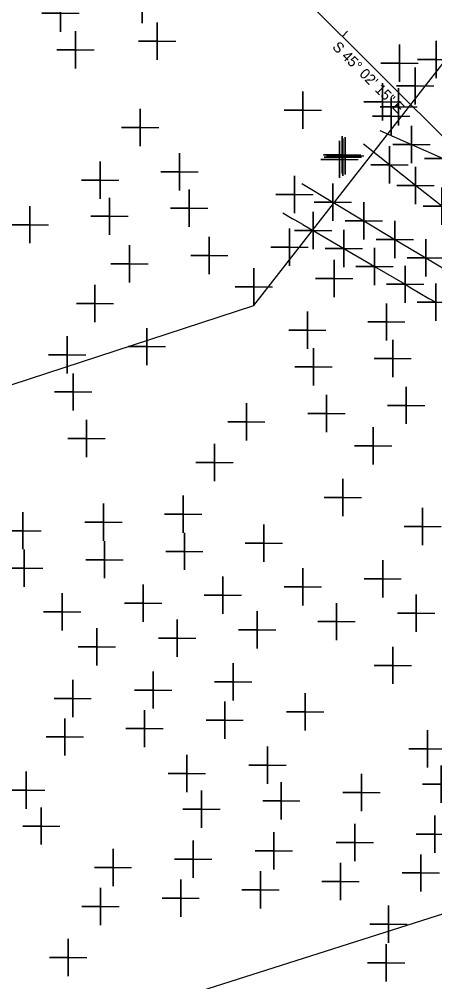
# Model space of a CAD drawing. Extents: x 2260968 to 2264340, y 653057 to 655850.
# Drawn here: x 2261248.1 to 2261303.8, y 655413.7 to 655542.8 of the extents above; entities that cross this region are included whole.
import ezdxf

# ---------------------------------------------------------------- set-up
doc = ezdxf.new("R2010")
doc.units = 0
for name, color, linetype in [('CL_X_Construction', 7, 'Continuous'), ('Default', 7, 'Continuous'), ('GE_X_CL_10', 7, 'Continuous'), ('GK_Patterns2', 7, 'Continuous')]:
    doc.layers.add(name, color=color, linetype=linetype)

msp = doc.modelspace()

# ---------------------------------------------------------------- linework, layer by layer
at = {"layer": 'CL_X_Construction'}
msp.add_line((2261256.04, 655575.83), (2261337.92, 655494.06), dxfattribs=at)
msp.add_line((2261256.04, 655575.83), (2261337.92, 655494.06), dxfattribs=at)
at = {"layer": 'Default'}
for points in [[(2261264.57, 655544.78), (2261264.57, 655547.28), (2261264.57, 655544.78), (2261262.07, 655544.78), (2261264.57, 655544.78), (2261264.57, 655542.28), (2261264.57, 655544.78), (2261267.07, 655544.78)], [(2261253.62, 655543.62), (2261253.62, 655546.12), (2261253.62, 655543.62), (2261251.12, 655543.62), (2261253.62, 655543.62), (2261253.62, 655541.12), (2261253.62, 655543.62), (2261256.12, 655543.62)], [(2261266.58, 655539.87), (2261266.58, 655542.37), (2261266.58, 655539.87), (2261264.08, 655539.87), (2261266.58, 655539.87), (2261266.58, 655537.37), (2261266.58, 655539.87), (2261269.08, 655539.87)], [(2261255.61, 655538.7), (2261255.61, 655541.2), (2261255.61, 655538.7), (2261253.11, 655538.7), (2261255.61, 655538.7), (2261255.61, 655536.2), (2261255.61, 655538.7), (2261258.11, 655538.7)], [(2261299.09, 655536.92), (2261299.09, 655539.42), (2261299.09, 655536.92), (2261296.59, 655536.92), (2261299.09, 655536.92), (2261299.09, 655534.42), (2261299.09, 655536.92), (2261301.59, 655536.92)], [(2261303.99, 655537.42), (2261303.99, 655539.92), (2261303.99, 655537.42), (2261301.49, 655537.42), (2261303.99, 655537.42), (2261303.99, 655534.92), (2261303.99, 655537.42), (2261306.49, 655537.42)], [(2261301.17, 655533.85), (2261301.17, 655536.35), (2261301.17, 655533.85), (2261298.67, 655533.85), (2261301.17, 655533.85), (2261301.17, 655531.35), (2261301.17, 655533.85), (2261303.67, 655533.85)], [(2261296.82, 655531.72), (2261296.82, 655534.22), (2261296.82, 655531.72), (2261294.32, 655531.72), (2261296.82, 655531.72), (2261296.82, 655529.22), (2261296.82, 655531.72), (2261299.32, 655531.72)], [(2261286.1, 655530.6), (2261286.1, 655533.1), (2261286.1, 655530.6), (2261283.6, 655530.6), (2261286.1, 655530.6), (2261286.1, 655528.1), (2261286.1, 655530.6), (2261288.6, 655530.6)], [(2261298.97, 655531.06), (2261298.97, 655533.56), (2261298.97, 655531.06), (2261296.47, 655531.06), (2261298.97, 655531.06), (2261298.97, 655528.56), (2261298.97, 655531.06), (2261301.47, 655531.06)], [(2261297.98, 655529.8), (2261297.98, 655532.3), (2261297.98, 655529.8), (2261295.48, 655529.8), (2261297.98, 655529.8), (2261297.98, 655527.3), (2261297.98, 655529.8), (2261300.48, 655529.8)], [(2261264.31, 655528.27), (2261264.31, 655530.77), (2261264.31, 655528.27), (2261261.81, 655528.27), (2261264.31, 655528.27), (2261264.31, 655525.77), (2261264.31, 655528.27), (2261266.81, 655528.27)], [(2261300.7, 655526), (2261300.7, 655528.5), (2261300.7, 655526), (2261298.2, 655526), (2261300.7, 655526), (2261300.7, 655523.5), (2261300.7, 655526), (2261303.2, 655526)], [(2261296.45, 655527.86), (2261300.7, 655526), (2261304.95, 655524.14), (2261309.21, 655522.28), (2261313.46, 655520.42), (2261317.72, 655518.56), (2261321.97, 655516.71), (2261326.22, 655514.85), (2261330.48, 655512.99), (2261334.73, 655511.13), (2261338.99, 655509.27), (2261343.24, 655507.41)], [(2261291.04, 655524.01), (2261291.04, 655526.51), (2261291.04, 655524.01), (2261288.54, 655524.01), (2261291.04, 655524.01), (2261291.04, 655521.51), (2261291.04, 655524.01), (2261293.54, 655524.01)], [(2261291.39, 655524.63), (2261291.39, 655527.13), (2261291.39, 655524.63), (2261288.89, 655524.63), (2261291.39, 655524.63), (2261291.39, 655522.13), (2261291.39, 655524.63), (2261293.89, 655524.63)], [(2261291.48, 655524.29), (2261291.48, 655526.79), (2261291.48, 655524.29), (2261288.98, 655524.29), (2261291.48, 655524.29), (2261291.48, 655521.79), (2261291.48, 655524.29), (2261293.98, 655524.29)], [(2261291.81, 655524.5), (2261291.81, 655527), (2261291.81, 655524.5), (2261289.31, 655524.5), (2261291.81, 655524.5), (2261291.81, 655522), (2261291.81, 655524.5), (2261294.31, 655524.5)], [(2261304.75, 655517.72), (2261301.24, 655520.5), (2261297.74, 655523.28), (2261294.24, 655526.06)], [(2261304.95, 655524.14), (2261304.95, 655526.64), (2261304.95, 655524.14), (2261302.45, 655524.14), (2261304.95, 655524.14), (2261304.95, 655521.64), (2261304.95, 655524.14), (2261307.45, 655524.14)], [(2261269.58, 655522.33), (2261269.58, 655524.83), (2261269.58, 655522.33), (2261267.08, 655522.33), (2261269.58, 655522.33), (2261269.58, 655519.83), (2261269.58, 655522.33), (2261272.08, 655522.33)], [(2261297.74, 655523.28), (2261297.74, 655525.78), (2261297.74, 655523.28), (2261295.24, 655523.28), (2261297.74, 655523.28), (2261297.74, 655520.78), (2261297.74, 655523.28), (2261300.24, 655523.28)], [(2261258.94, 655521.23), (2261258.94, 655523.73), (2261258.94, 655521.23), (2261256.44, 655521.23), (2261258.94, 655521.23), (2261258.94, 655518.73), (2261258.94, 655521.23), (2261261.44, 655521.23)], [(2261301.24, 655520.5), (2261301.24, 655523), (2261301.24, 655520.5), (2261298.74, 655520.5), (2261301.24, 655520.5), (2261301.24, 655518), (2261301.24, 655520.5), (2261303.74, 655520.5)], [(2261285.01, 655519.29), (2261285.01, 655521.79), (2261285.01, 655519.29), (2261282.51, 655519.29), (2261285.01, 655519.29), (2261285.01, 655516.79), (2261285.01, 655519.29), (2261287.51, 655519.29)], [(2261285.98, 655520.77), (2261290.14, 655518.27), (2261294.3, 655515.78), (2261298.46, 655513.28), (2261302.63, 655510.79), (2261306.79, 655508.29)], [(2261290.14, 655518.27), (2261290.14, 655520.77), (2261290.14, 655518.27), (2261287.64, 655518.27), (2261290.14, 655518.27), (2261290.14, 655515.77), (2261290.14, 655518.27), (2261292.64, 655518.27)], [(2261270.87, 655517.48), (2261270.87, 655519.98), (2261270.87, 655517.48), (2261268.37, 655517.48), (2261270.87, 655517.48), (2261270.87, 655514.98), (2261270.87, 655517.48), (2261273.37, 655517.48)], [(2261304.75, 655517.72), (2261304.75, 655520.22), (2261304.75, 655517.72), (2261302.25, 655517.72), (2261304.75, 655517.72), (2261304.75, 655515.22), (2261304.75, 655517.72), (2261307.25, 655517.72)], [(2261260.17, 655516.37), (2261260.17, 655518.87), (2261260.17, 655516.37), (2261257.67, 655516.37), (2261260.17, 655516.37), (2261260.17, 655513.87), (2261260.17, 655516.37), (2261262.67, 655516.37)], [(2261294.3, 655515.78), (2261294.3, 655518.28), (2261294.3, 655515.78), (2261291.8, 655515.78), (2261294.3, 655515.78), (2261294.3, 655513.28), (2261294.3, 655515.78), (2261296.8, 655515.78)], [(2261249.49, 655515.25), (2261249.49, 655517.75), (2261249.49, 655515.25), (2261246.99, 655515.25), (2261249.49, 655515.25), (2261249.49, 655512.75), (2261249.49, 655515.25), (2261251.99, 655515.25)], [(2261287.52, 655514.45), (2261287.52, 655516.95), (2261287.52, 655514.45), (2261285.02, 655514.45), (2261287.52, 655514.45), (2261287.52, 655511.95), (2261287.52, 655514.45), (2261290.02, 655514.45)], [(2261283.42, 655516.85), (2261284.7, 655516.1), (2261285.04, 655515.9), (2261286.08, 655515.3), (2261286.13, 655515.26), (2261287.08, 655514.71), (2261287.52, 655514.45), (2261291.18, 655512.31), (2261291.63, 655512.05), (2261295.13, 655510), (2261295.73, 655509.65), (2261299.84, 655507.25), (2261300.59, 655506.8), (2261303.04, 655505.37), (2261303.95, 655504.84)], [(2261298.46, 655513.28), (2261298.46, 655515.78), (2261298.46, 655513.28), (2261295.96, 655513.28), (2261298.46, 655513.28), (2261298.46, 655510.78), (2261298.46, 655513.28), (2261300.96, 655513.28)], [(2261284.33, 655512.22), (2261284.33, 655514.72), (2261284.33, 655512.22), (2261281.83, 655512.22), (2261284.33, 655512.22), (2261284.33, 655509.72), (2261284.33, 655512.22), (2261286.83, 655512.22)], [(2261291.63, 655512.05), (2261291.63, 655514.55), (2261291.63, 655512.05), (2261289.13, 655512.05), (2261291.63, 655512.05), (2261291.63, 655509.55), (2261291.63, 655512.05), (2261294.13, 655512.05)], [(2261273.57, 655511.11), (2261273.57, 655513.61), (2261273.57, 655511.11), (2261271.07, 655511.11), (2261273.57, 655511.11), (2261273.57, 655508.61), (2261273.57, 655511.11), (2261276.07, 655511.11)], [(2261302.63, 655510.79), (2261302.63, 655513.29), (2261302.63, 655510.79), (2261300.13, 655510.79), (2261302.63, 655510.79), (2261302.63, 655508.29), (2261302.63, 655510.79), (2261305.13, 655510.79)], [(2261262.88, 655510.01), (2261262.88, 655512.51), (2261262.88, 655510.01), (2261260.38, 655510.01), (2261262.88, 655510.01), (2261262.88, 655507.51), (2261262.88, 655510.01), (2261265.38, 655510.01)], [(2261295.73, 655509.65), (2261295.73, 655512.15), (2261295.73, 655509.65), (2261293.23, 655509.65), (2261295.73, 655509.65), (2261295.73, 655507.15), (2261295.73, 655509.65), (2261298.23, 655509.65)], [(2261290.31, 655508.03), (2261290.31, 655510.53), (2261290.31, 655508.03), (2261287.81, 655508.03), (2261290.31, 655508.03), (2261290.31, 655505.53), (2261290.31, 655508.03), (2261292.81, 655508.03)], [(2261279.55, 655506.9), (2261279.55, 655509.4), (2261279.55, 655506.9), (2261277.05, 655506.9), (2261279.55, 655506.9), (2261279.55, 655504.4), (2261279.55, 655506.9), (2261282.05, 655506.9)], [(2261299.84, 655507.25), (2261299.84, 655509.75), (2261299.84, 655507.25), (2261297.34, 655507.25), (2261299.84, 655507.25), (2261299.84, 655504.75), (2261299.84, 655507.25), (2261302.34, 655507.25)], [(2261258.23, 655504.68), (2261258.23, 655507.18), (2261258.23, 655504.68), (2261255.73, 655504.68), (2261258.23, 655504.68), (2261258.23, 655502.18), (2261258.23, 655504.68), (2261260.73, 655504.68)], [(2261303.95, 655504.84), (2261303.95, 655507.34), (2261303.95, 655504.84), (2261301.45, 655504.84), (2261303.95, 655504.84), (2261303.95, 655502.34), (2261303.95, 655504.84), (2261306.45, 655504.84)], [(2261297.32, 655502.2), (2261297.32, 655504.7), (2261297.32, 655502.2), (2261294.82, 655502.2), (2261297.32, 655502.2), (2261297.32, 655499.7), (2261297.32, 655502.2), (2261299.82, 655502.2)], [(2261286.72, 655501.12), (2261286.72, 655503.62), (2261286.72, 655501.12), (2261284.22, 655501.12), (2261286.72, 655501.12), (2261286.72, 655498.62), (2261286.72, 655501.12), (2261289.22, 655501.12)], [(2261265.17, 655498.89), (2261265.17, 655501.39), (2261265.17, 655498.89), (2261262.67, 655498.89), (2261265.17, 655498.89), (2261265.17, 655496.39), (2261265.17, 655498.89), (2261267.67, 655498.89)], [(2261254.5, 655497.79), (2261254.5, 655500.29), (2261254.5, 655497.79), (2261252, 655497.79), (2261254.5, 655497.79), (2261254.5, 655495.29), (2261254.5, 655497.79), (2261257, 655497.79)], [(2261298.17, 655497.29), (2261298.17, 655499.79), (2261298.17, 655497.29), (2261295.67, 655497.29), (2261298.17, 655497.29), (2261298.17, 655494.79), (2261298.17, 655497.29), (2261300.67, 655497.29)], [(2261287.53, 655496.18), (2261287.53, 655498.68), (2261287.53, 655496.18), (2261285.03, 655496.18), (2261287.53, 655496.18), (2261287.53, 655493.68), (2261287.53, 655496.18), (2261290.03, 655496.18)], [(2261255.29, 655492.81), (2261255.29, 655495.31), (2261255.29, 655492.81), (2261252.79, 655492.81), (2261255.29, 655492.81), (2261255.29, 655490.31), (2261255.29, 655492.81), (2261257.79, 655492.81)], [(2261289.29, 655489.92), (2261289.29, 655492.42), (2261289.29, 655489.92), (2261286.79, 655489.92), (2261289.29, 655489.92), (2261289.29, 655487.42), (2261289.29, 655489.92), (2261291.79, 655489.92)], [(2261299.97, 655491.02), (2261299.97, 655493.52), (2261299.97, 655491.02), (2261297.47, 655491.02), (2261299.97, 655491.02), (2261299.97, 655488.52), (2261299.97, 655491.02), (2261302.47, 655491.02)], [(2261278.54, 655488.81), (2261278.54, 655491.31), (2261278.54, 655488.81), (2261276.04, 655488.81), (2261278.54, 655488.81), (2261278.54, 655486.31), (2261278.54, 655488.81), (2261281.04, 655488.81)], [(2261257.08, 655486.59), (2261257.08, 655489.09), (2261257.08, 655486.59), (2261254.58, 655486.59), (2261257.08, 655486.59), (2261257.08, 655484.09), (2261257.08, 655486.59), (2261259.58, 655486.59)], [(2261295.56, 655485.59), (2261295.56, 655488.09), (2261295.56, 655485.59), (2261293.06, 655485.59), (2261295.56, 655485.59), (2261295.56, 655483.09), (2261295.56, 655485.59), (2261298.06, 655485.59)], [(2261274.27, 655483.37), (2261274.27, 655485.87), (2261274.27, 655483.37), (2261271.77, 655483.37), (2261274.27, 655483.37), (2261274.27, 655480.87), (2261274.27, 655483.37), (2261276.77, 655483.37)], [(2261291.5, 655478.65), (2261291.5, 655481.15), (2261291.5, 655478.65), (2261289, 655478.65), (2261291.5, 655478.65), (2261291.5, 655476.15), (2261291.5, 655478.65), (2261294, 655478.65)], [(2261270.05, 655476.44), (2261270.05, 655478.94), (2261270.05, 655476.44), (2261267.55, 655476.44), (2261270.05, 655476.44), (2261270.05, 655473.94), (2261270.05, 655476.44), (2261272.55, 655476.44)], [(2261259.38, 655475.34), (2261259.38, 655477.84), (2261259.38, 655475.34), (2261256.88, 655475.34), (2261259.38, 655475.34), (2261259.38, 655472.84), (2261259.38, 655475.34), (2261261.88, 655475.34)], [(2261302.19, 655474.77), (2261302.19, 655477.27), (2261302.19, 655474.77), (2261299.69, 655474.77), (2261302.19, 655474.77), (2261302.19, 655472.27), (2261302.19, 655474.77), (2261304.69, 655474.77)], [(2261248.53, 655474.21), (2261248.53, 655476.71), (2261248.53, 655474.21), (2261246.03, 655474.21), (2261248.53, 655474.21), (2261248.53, 655471.71), (2261248.53, 655474.21), (2261251.03, 655474.21)], [(2261280.89, 655472.55), (2261280.89, 655475.05), (2261280.89, 655472.55), (2261278.39, 655472.55), (2261280.89, 655472.55), (2261280.89, 655470.05), (2261280.89, 655472.55), (2261283.39, 655472.55)], [(2261270.22, 655471.44), (2261270.22, 655473.94), (2261270.22, 655471.44), (2261267.72, 655471.44), (2261270.22, 655471.44), (2261270.22, 655468.94), (2261270.22, 655471.44), (2261272.72, 655471.44)], [(2261259.52, 655470.32), (2261259.52, 655472.82), (2261259.52, 655470.32), (2261257.02, 655470.32), (2261259.52, 655470.32), (2261259.52, 655467.82), (2261259.52, 655470.32), (2261262.02, 655470.32)], [(2261248.73, 655469.18), (2261248.73, 655471.68), (2261248.73, 655469.18), (2261246.23, 655469.18), (2261248.73, 655469.18), (2261248.73, 655466.68), (2261248.73, 655469.18), (2261251.23, 655469.18)], [(2261286.11, 655466.67), (2261286.11, 655469.17), (2261286.11, 655466.67), (2261283.61, 655466.67), (2261286.11, 655466.67), (2261286.11, 655464.17), (2261286.11, 655466.67), (2261288.61, 655466.67)], [(2261296.83, 655467.77), (2261296.83, 655470.27), (2261296.83, 655467.77), (2261294.33, 655467.77), (2261296.83, 655467.77), (2261296.83, 655465.27), (2261296.83, 655467.77), (2261299.33, 655467.77)], [(2261275.38, 655465.57), (2261275.38, 655468.07), (2261275.38, 655465.57), (2261272.88, 655465.57), (2261275.38, 655465.57), (2261275.38, 655463.07), (2261275.38, 655465.57), (2261277.88, 655465.57)], [(2261264.69, 655464.47), (2261264.69, 655466.97), (2261264.69, 655464.47), (2261262.19, 655464.47), (2261264.69, 655464.47), (2261264.69, 655461.97), (2261264.69, 655464.47), (2261267.19, 655464.47)], [(2261253.82, 655463.33), (2261253.82, 655465.83), (2261253.82, 655463.33), (2261251.32, 655463.33), (2261253.82, 655463.33), (2261253.82, 655460.83), (2261253.82, 655463.33), (2261256.32, 655463.33)], [(2261301.31, 655463.13), (2261301.31, 655465.63), (2261301.31, 655463.13), (2261298.81, 655463.13), (2261301.31, 655463.13), (2261301.31, 655460.63), (2261301.31, 655463.13), (2261303.81, 655463.13)], [(2261290.64, 655462.01), (2261290.64, 655464.51), (2261290.64, 655462.01), (2261288.14, 655462.01), (2261290.64, 655462.01), (2261290.64, 655459.51), (2261290.64, 655462.01), (2261293.14, 655462.01)], [(2261279.99, 655460.91), (2261279.99, 655463.41), (2261279.99, 655460.91), (2261277.49, 655460.91), (2261279.99, 655460.91), (2261279.99, 655458.41), (2261279.99, 655460.91), (2261282.49, 655460.91)], [(2261269.26, 655459.78), (2261269.26, 655462.28), (2261269.26, 655459.78), (2261266.76, 655459.78), (2261269.26, 655459.78), (2261269.26, 655457.28), (2261269.26, 655459.78), (2261271.76, 655459.78)], [(2261258.47, 655458.64), (2261258.47, 655461.14), (2261258.47, 655458.64), (2261255.97, 655458.64), (2261258.47, 655458.64), (2261258.47, 655456.14), (2261258.47, 655458.64), (2261260.97, 655458.64)], [(2261298.2, 655456.15), (2261298.2, 655458.65), (2261298.2, 655456.15), (2261295.7, 655456.15), (2261298.2, 655456.15), (2261298.2, 655453.65), (2261298.2, 655456.15), (2261300.7, 655456.15)], [(2261276.77, 655453.94), (2261276.77, 655456.44), (2261276.77, 655453.94), (2261274.27, 655453.94), (2261276.77, 655453.94), (2261276.77, 655451.44), (2261276.77, 655453.94), (2261279.27, 655453.94)], [(2261266.03, 655452.84), (2261266.03, 655455.34), (2261266.03, 655452.84), (2261263.53, 655452.84), (2261266.03, 655452.84), (2261266.03, 655450.34), (2261266.03, 655452.84), (2261268.53, 655452.84)], [(2261255.24, 655451.72), (2261255.24, 655454.22), (2261255.24, 655451.72), (2261252.74, 655451.72), (2261255.24, 655451.72), (2261255.24, 655449.22), (2261255.24, 655451.72), (2261257.74, 655451.72)], [(2261286.44, 655449.92), (2261286.44, 655452.42), (2261286.44, 655449.92), (2261283.94, 655449.92), (2261286.44, 655449.92), (2261286.44, 655447.42), (2261286.44, 655449.92), (2261288.94, 655449.92)], [(2261275.63, 655448.79), (2261275.63, 655451.29), (2261275.63, 655448.79), (2261273.13, 655448.79), (2261275.63, 655448.79), (2261275.63, 655446.29), (2261275.63, 655448.79), (2261278.13, 655448.79)], [(2261264.87, 655447.66), (2261264.87, 655450.16), (2261264.87, 655447.66), (2261262.37, 655447.66), (2261264.87, 655447.66), (2261264.87, 655445.16), (2261264.87, 655447.66), (2261267.37, 655447.66)], [(2261254.17, 655446.54), (2261254.17, 655449.04), (2261254.17, 655446.54), (2261251.67, 655446.54), (2261254.17, 655446.54), (2261254.17, 655444.04), (2261254.17, 655446.54), (2261256.67, 655446.54)], [(2261302.82, 655444.97), (2261302.82, 655447.47), (2261302.82, 655444.97), (2261300.32, 655444.97), (2261302.82, 655444.97), (2261302.82, 655442.47), (2261302.82, 655444.97), (2261305.32, 655444.97)], [(2261281.36, 655442.76), (2261281.36, 655445.26), (2261281.36, 655442.76), (2261278.86, 655442.76), (2261281.36, 655442.76), (2261281.36, 655440.26), (2261281.36, 655442.76), (2261283.86, 655442.76)], [(2261270.54, 655441.63), (2261270.54, 655444.13), (2261270.54, 655441.63), (2261268.04, 655441.63), (2261270.54, 655441.63), (2261270.54, 655439.13), (2261270.54, 655441.63), (2261273.04, 655441.63)], [(2261304.67, 655440.22), (2261304.67, 655442.72), (2261304.67, 655440.22), (2261302.17, 655440.22), (2261304.67, 655440.22), (2261304.67, 655437.72), (2261304.67, 655440.22), (2261307.17, 655440.22)], [(2261249.02, 655439.41), (2261249.02, 655441.91), (2261249.02, 655439.41), (2261246.52, 655439.41), (2261249.02, 655439.41), (2261249.02, 655436.91), (2261249.02, 655439.41), (2261251.52, 655439.41)], [(2261293.98, 655439.11), (2261293.98, 655441.61), (2261293.98, 655439.11), (2261291.48, 655439.11), (2261293.98, 655439.11), (2261293.98, 655436.61), (2261293.98, 655439.11), (2261296.48, 655439.11)], [(2261283.23, 655437.98), (2261283.23, 655440.48), (2261283.23, 655437.98), (2261280.73, 655437.98), (2261283.23, 655437.98), (2261283.23, 655435.48), (2261283.23, 655437.98), (2261285.73, 655437.98)], [(2261272.52, 655436.85), (2261272.52, 655439.35), (2261272.52, 655436.85), (2261270.02, 655436.85), (2261272.52, 655436.85), (2261272.52, 655434.35), (2261272.52, 655436.85), (2261275.02, 655436.85)], [(2261251.03, 655434.6), (2261251.03, 655437.1), (2261251.03, 655434.6), (2261248.53, 655434.6), (2261251.03, 655434.6), (2261251.03, 655432.1), (2261251.03, 655434.6), (2261253.53, 655434.6)], [(2261303.83, 655433.49), (2261303.83, 655435.99), (2261303.83, 655433.49), (2261301.33, 655433.49), (2261303.83, 655433.49), (2261303.83, 655430.99), (2261303.83, 655433.49), (2261306.33, 655433.49)], [(2261293.08, 655432.38), (2261293.08, 655434.88), (2261293.08, 655432.38), (2261290.58, 655432.38), (2261293.08, 655432.38), (2261293.08, 655429.88), (2261293.08, 655432.38), (2261295.58, 655432.38)], [(2261282.24, 655431.26), (2261282.24, 655433.76), (2261282.24, 655431.26), (2261279.74, 655431.26), (2261282.24, 655431.26), (2261282.24, 655428.76), (2261282.24, 655431.26), (2261284.74, 655431.26)], [(2261271.42, 655430.14), (2261271.42, 655432.64), (2261271.42, 655430.14), (2261268.92, 655430.14), (2261271.42, 655430.14), (2261271.42, 655427.64), (2261271.42, 655430.14), (2261273.92, 655430.14)], [(2261260.65, 655429.02), (2261260.65, 655431.52), (2261260.65, 655429.02), (2261258.15, 655429.02), (2261260.65, 655429.02), (2261260.65, 655426.52), (2261260.65, 655429.02), (2261263.15, 655429.02)], [(2261301.95, 655428.3), (2261301.95, 655430.8), (2261301.95, 655428.3), (2261299.45, 655428.3), (2261301.95, 655428.3), (2261301.95, 655425.8), (2261301.95, 655428.3), (2261304.45, 655428.3)], [(2261291.16, 655427.17), (2261291.16, 655429.67), (2261291.16, 655427.17), (2261288.66, 655427.17), (2261291.16, 655427.17), (2261291.16, 655424.67), (2261291.16, 655427.17), (2261293.66, 655427.17)], [(2261280.42, 655426.04), (2261280.42, 655428.54), (2261280.42, 655426.04), (2261277.92, 655426.04), (2261280.42, 655426.04), (2261280.42, 655423.54), (2261280.42, 655426.04), (2261282.92, 655426.04)], [(2261269.73, 655424.93), (2261269.73, 655427.43), (2261269.73, 655424.93), (2261267.23, 655424.93), (2261269.73, 655424.93), (2261269.73, 655422.43), (2261269.73, 655424.93), (2261272.23, 655424.93)], [(2261258.98, 655423.8), (2261258.98, 655426.3), (2261258.98, 655423.8), (2261256.48, 655423.8), (2261258.98, 655423.8), (2261258.98, 655421.3), (2261258.98, 655423.8), (2261261.48, 655423.8)], [(2261297.6, 655421.42), (2261297.6, 655423.92), (2261297.6, 655421.42), (2261295.1, 655421.42), (2261297.6, 655421.42), (2261297.6, 655418.92), (2261297.6, 655421.42), (2261300.1, 655421.42)], [(2261254.65, 655416.98), (2261254.65, 655419.48), (2261254.65, 655416.98), (2261252.15, 655416.98), (2261254.65, 655416.98), (2261254.65, 655414.48), (2261254.65, 655416.98), (2261257.15, 655416.98)], [(2261297.31, 655416.25), (2261297.31, 655418.75), (2261297.31, 655416.25), (2261294.81, 655416.25), (2261297.31, 655416.25), (2261297.31, 655413.75), (2261297.31, 655416.25), (2261299.81, 655416.25)]]:
    msp.add_lwpolyline(points, dxfattribs=at)
at = {"layer": 'GE_X_CL_10'}
for p, q in [((2261256.04, 655575.83), (2261337.92, 655494.06)), ((2261291.42, 655540.5), (2261292.13, 655541.21)), ((2261291.42, 655540.5), (2261292.13, 655541.21))]:
    msp.add_line(p, q, dxfattribs=at)
at = {"layer": 'GK_Patterns2'}
for points in [[(2260985.64, 655408.37), (2261279.55, 655504.4), (2261315.3, 655550.25), (2261423.87, 655621.66)], [(2261000.71, 655326.07), (2261387.67, 655449.15), (2261465.76, 655603.57)]]:
    msp.add_lwpolyline(points, dxfattribs=at)

# ---------------------------------------------------------------- texts
at = {"layer": 'GE_X_CL_10'}
msp.add_text('S 45%%d 02\' 15" E', height=1.4, rotation=315.0375, dxfattribs=at).set_placement((2261289.98, 655538.98))

doc.saveas('drawing.dxf')
